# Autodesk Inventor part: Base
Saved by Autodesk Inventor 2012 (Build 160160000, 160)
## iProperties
Created: 2013-08
Part Number: Base
Material: Default
Document SubType Name: Modeling
Designer: hilarion
Density: 1 g/cm^3
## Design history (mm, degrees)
node "Base2"
node "Base"
node "Base1"
